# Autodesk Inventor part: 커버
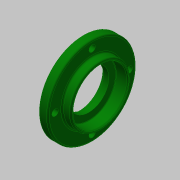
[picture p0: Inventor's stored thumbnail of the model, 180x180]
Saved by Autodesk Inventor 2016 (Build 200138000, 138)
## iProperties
Created: 2018-11
Part Number: 커버
Material: 알루미늄 6061
Document SubType Name: Modeling
Designer: mduedu
Density: 1 g/cm^3
Appearance: 진녹색
Author: mduedu
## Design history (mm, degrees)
sketch "스케치1"
  geometry: L1 (0, 0)-(3, 0); L2 (3, 0)-(3, 20); L3 (3, 20)-(0, 20); L4 (0, 20)-(0, 0); L5 (3, 0)-(9, 0); L6 (9, 0)-(9, 31); L7 (9, 31)-(3, 31); L8 (3, 31)-(3, 0); L9 (9, 0)-(15, 0); L10 (15, 0)-(15, 21); L11 (15, 21)-(9, 21); L12 (9, 21)-(9, 0)
  constraints: 24 end point, 6 parallel, 3 horizontal, 3 perpendicular
  dimensions: "d0" = 62 diameter of L7 L5; "d2" = 42 diameter of L11 L9; "d3" = 40 diameter of L3 L1; "d4" = 3 distance of L2.end L3.end; "d5" = 6 distance of L6.end L7.end; "d6" = 15 distance between parallel lines of L10 L4
revolve "회전1" sketch "스케치1" stored, may be unused: angle "d7" = 90 deg
sketch "스케치2"
  geometry: L1 (0, -20)-(0, 20) reference; L2 (0, 20)-(3, 20) reference; L3 (3, 20)-(3, 31) reference; L4 (3, 31)-(9, 31) reference; L5 (9, 31)-(9, 21) reference; L6 (9, 21)-(15, 21) reference; L7 (15, 21)-(15, -21) reference; L8 (15, -21)-(9, -21) reference; L9 (9, -21)-(9, -31) reference; L10 (9, -31)-(3, -31) reference; L11 (3, -31)-(3, -20) reference; L12 (3, -20)-(0, -20) reference; L13 (0, 0)-(3, 0); L14 (3, 0)-(3, 16.5); L15 (3, 16.5)-(0, 16.5); L16 (0, 16.5)-(0, 0); L17 (3, 0)-(6.7, 0); L18 (6.7, 0)-(6.7, 14); L19 (6.7, 14)-(3, 14); L20 (3, 14)-(3, 0); L21 (6.7, 0)-(15, 0); L22 (15, 0)-(15, 19); L23 (15, 19)-(6.7, 19); L24 (6.7, 19)-(6.7, 0)
  constraints: 24 end point, 6 parallel, 3 horizontal, 3 perpendicular, 1 point on line
  dimensions: "d8" = 38 diameter of L23 L21; "d10" = 28 diameter of L19 L17; "d11" = 33 diameter of L15 L13; "d12" = 3 distance of L14.end L15.end; "d13" = 8.3 distance of L22.end L23.end
revolve "회전2" sketch "스케치2" stored, may be unused: angle "d14" = 90 deg
fillet "모깎기1" dims "d15" = 0.3
chamfer "모따기1" distance "d16" = 0.8; stored, may be unused: second distance "d17" = 2, angle "d18" = 30 deg
fillet "모깎기2" dims "d19" = 1
chamfer "모따기2" distance "d20" = 0.5; stored, may be unused: second distance "d21" = 2, angle "d22" = 30 deg
sketch "스케치3" dims "d23" = 52
  geometry: 6 further points
  constraints: 2 vertical alignment, 1 coincident, 7 other
  dimensions: "d26" = 360 deg dimension on point (0, 0) point (0, 26) (derived)
sketch "스케치4"
  geometry: 4 further points
  constraints: 4 other
hole "구멍1" sketch "스케치4" at (-26, 0), (0, -26), (26, 0), (0, 26) diameter "d28" = 4.5; stored, may be unused: countersink angle "d32" = 90 deg, drill point angle "d34" = 0 deg; dims "d29" = 6, "d30" = 8, "d31" = 4.6, "d33" = 8
node "솔리드1"
node "절단 모서리 투영1"
